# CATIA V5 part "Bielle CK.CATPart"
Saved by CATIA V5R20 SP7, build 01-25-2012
Part number: Bielle CK
Publications: "Point.1", "Point.2", "Droite.2", "Droite.3"
Bounding box of the stored display mesh (mm): x -10 to 10, y 0 to 0, z -450 to 0
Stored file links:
  U:\IAO\IAO\IAO\Bielle CK.CATPart
  U:\IAO\IAO\IAO\Squelette.CATProduct
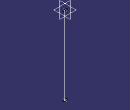
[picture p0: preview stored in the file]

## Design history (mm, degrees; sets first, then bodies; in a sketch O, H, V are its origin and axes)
External parameters (linked from other documents)
  `External.Longueur X4` = 450 mm
  `External.Longueur Demi Pivot` = 10 mm
Body1 (main body)
  Point1: (0, 0, 0)
  Line1: type Normal, RefPoint Point1, RefSkin xy-plane, Start 0, End 450 {= `External.Longueur X4`}
  Point2: (0, 0, 0), relative to vertex of Line1
  Line2: type PtDir, RefPoint Point1, Direction yz-plane, Start -10, End 10 {= `External.Longueur Demi Pivot`}
  Line3: type PtDir, RefPoint Point2, Direction yz-plane, Start -10, End 10 {= `External.Longueur Demi Pivot`}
